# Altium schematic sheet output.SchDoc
size A4
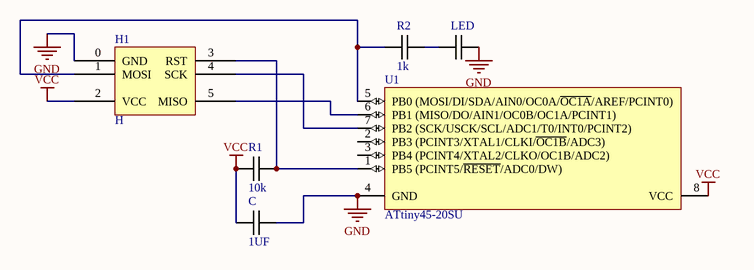
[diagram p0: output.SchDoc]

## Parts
C  1UF  [1206C-GENERIC]
H1  H  [smdHeader 2x3]
LED  (no value)  [1206C-GENERIC]
R1  10k  [1206C-GENERIC]
R2  1k  [1206C-GENERIC]
U1  ATtiny45-20SU  [8S2_N]

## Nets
GND: C.2 H1.0(GND) LED.2 U1.4(GND)
VCC: C.1 H1.2(VCC) R1.1 U1.8(VCC)
NetH1_1: H1.1(MOSI) R2.1 U1.5(PB0_(MOSI/DI/SDA/AIN0/OC0A/~{OC1A}/AREF/PCINT0))
NetH1_3: H1.3(RST) R1.2 U1.1(PB5_(PCINT5/~{RESET}/ADC0/DW))
NetH1_4: H1.4(SCK) U1.7(PB2_(SCK/USCK/SCL/ADC1/T0/INT0/PCINT2))
NetH1_5: H1.5(MISO) U1.6(PB1_(MISO/DO/AIN1/OC0B/OC1A/PCINT1))
NetLED_1: LED.1 R2.2

Not connected (* = marked no-connect by the designer): U1 2(PB3_(PCINT3/XTAL1/CLKI/~{OC1B}/ADC3)) 3(PB4_(PCINT4/XTAL2/CLKO/OC1B/ADC2))

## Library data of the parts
C LED R1 R2 = 1206C-10U-35V-X7R: GENERIC CAPACITOR NON POLARISED 1206; Manufacturer Part Number: GMK316F106ZL-T; Manufacturer: Taiyo Yuden; Reel: C90
H1 = smadheader 2x3
U1 = ATtiny45-20SU: Low Power tinyAVR® 8-Bit Microcontroller, 4K Flash Memory, 20MHz, Industrial Temperature, 8-Lead SOIC, Pb-Free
